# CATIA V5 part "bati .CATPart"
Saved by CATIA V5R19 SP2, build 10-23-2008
Part number: bati 
Material "Aucun"
Bounding box of the stored display mesh (mm): x -20 to 20, y -50 to 50, z -4 to 40.312
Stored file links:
  F:\Projet CAO\pièces et assemblages\mécanisme 577\577-SaintAime\577-SaintAime\bati .CATPart
  F:\Projet CAO\pièces et assemblages\mécanisme 577\577-SaintAime\577-SaintAime\mecanisme577_parametre.CATProduct
  C:\Appli\Dassault Systemes\B19\intel_a\startup\materials\French\Catalog.CATMaterial
  C:\Appli\Dassault Systemes\B19\intel_a\startup\materials\solar_panel.jpg
  C:\Appli\Dassault Systemes\B19\intel_a\startup\materials\blue_env_512x512.jpg
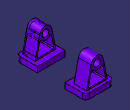
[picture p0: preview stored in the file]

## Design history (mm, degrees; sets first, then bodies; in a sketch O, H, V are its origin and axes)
External parameters (linked from other documents)
  External.largeur_pivot = 18 mm
  External.diam_pivot = 5 mm
Set1
  Plane1: type Offset, RefPlane zx-plane, Offset 37, reversed
Body1 (main body)
  Sketch1 on yz-plane, origin (0, 0, 0), H (0, 1, 0), V (0, 0, 1)
    line L1 (-50, 4) -> (-20, 4)
    line L2 (50, 4) -> (50, -4)
    line L3 (50, -4) -> (20, -4)
    line L4 (-50, -4) -> (-50, 4)
    line L5 (-20, 4) -> (-20, -4)
    point P6 (-20, -4)
    point P7 (20, 4)
    line L6 (20, 4) -> (20, -4)
    line L7 (20, 4) -> (50, 4)
    line L8 (-20, -4) -> (-50, -4)
    distance L1 L3 = 8
    distance L6 L2 = 30
    distance L2 L4 = 100
    horizontal: L1 H, L3 H, L7 H, L8 H
    vertical: L2 V, L4 V, L5 V, L6 V
    symmetry: L2 L4 V, L3 L1 H, L6 L5 V
    coincidence: P6 L3, P7 L1, L1 L7, L3 L8
  Pad1: profile Sketch1, direction (1, 0, 0), length 20, mirrored extent
  Sketch2 on Plane1, origin (0, -37, 0), H (-1, 0, 0), V (0, 0, 1)
    line L1 (15, 4) -> (8.8059, 33.3405)
    arc A1 centre (0, 31.4815) radius 9 from (8.8059, 33.3405) to (-8.8059, 33.3405) ccw
    point P3 (0, 31.4815)
    line L2 (-8.8059, 33.3405) -> (-15, 4)
    circle A2 centre (0, 31.4815) radius 5
    line L3 (15, 4) -> (-15, 4)
    reference projected line E1 (40, 4) -> (-40, 4) from edge [face of Pad1 from Sketch1.L4 | face of Pad1 from Sketch1.L1]
    line L4 (-11.3005, 6) -> (11.3005, 6)
    line L5 (12.279, 7.2066) -> (8.5015, 25.0999)
    point P7 (8.0175, 27.3926)
    line L6 (-12.279, 7.2066) -> (-8.5015, 25.0999)
    point P8 (-8.0175, 27.3926)
    arc A3 centre (0, 31.4815) radius 9 from (-6.7708, 25.5522) to (6.7708, 25.5522) ccw
    point P9 (0, 31.4815)
    arc A4 centre (7.5231, 24.8934) radius 1 from (6.7708, 25.5522) to (8.5015, 25.0999) cw
    arc A5 centre (-7.5231, 24.8934) radius 1 from (-6.7708, 25.5522) to (-8.5015, 25.0999) ccw
    arc A6 centre (11.3005, 7) radius 1 from (11.3005, 6) to (12.279, 7.2066) ccw
    arc A7 centre (-11.3005, 7) radius 1 from (-11.3005, 6) to (-12.279, 7.2066) cw
    radius A2 = 5 {= External.diam_pivot}
    length L3 = 30
    radius A1 = 9 {= External.diam_pivot + 4mm}
    distance L4 L3 = 2
    distance L5 L1 = 2
    radius A4 = 1
    radius A5 = 1
    radius A6 = 1
    radius A7 = 1
    distance A3 A2 = 4
    distance P9 L3 = 27.4815
    tangency: A1 L1, L2 A1, A4 A3, A4 L5, A5 L6, A5 A3, A6 L4, A6 L5, A7 L4, A7 L6
    symmetry: L2 L1 V, L6 L5 V
    coincidence: P3 V, L3 E1, A3 P7, L5 P7, A3 P8, L6 P8
    concentricity: A2 A1, A3 A1
    horizontal: L3 H, L4 H
    parallelism: L6 L2
  Pad2: profile Sketch2, direction (0, 1, 0), length 9 {= External.largeur_pivot / 2}, mirrored extent
  Mirror1: of Pad2, Sketch2, about zx-plane
  Fillet1: radius 5, on edge [face of Pad1 from Sketch1.L4 | end face of Pad1]; edge [face of Pad1 from Sketch1.L2 | end face of Pad1]; edge [start face of Pad1 | face of Pad1 from Sketch1.L2]; edge [start face of Pad1 | face of Pad1 from Sketch1.L4]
